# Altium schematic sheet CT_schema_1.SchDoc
size 405 x 258 mm
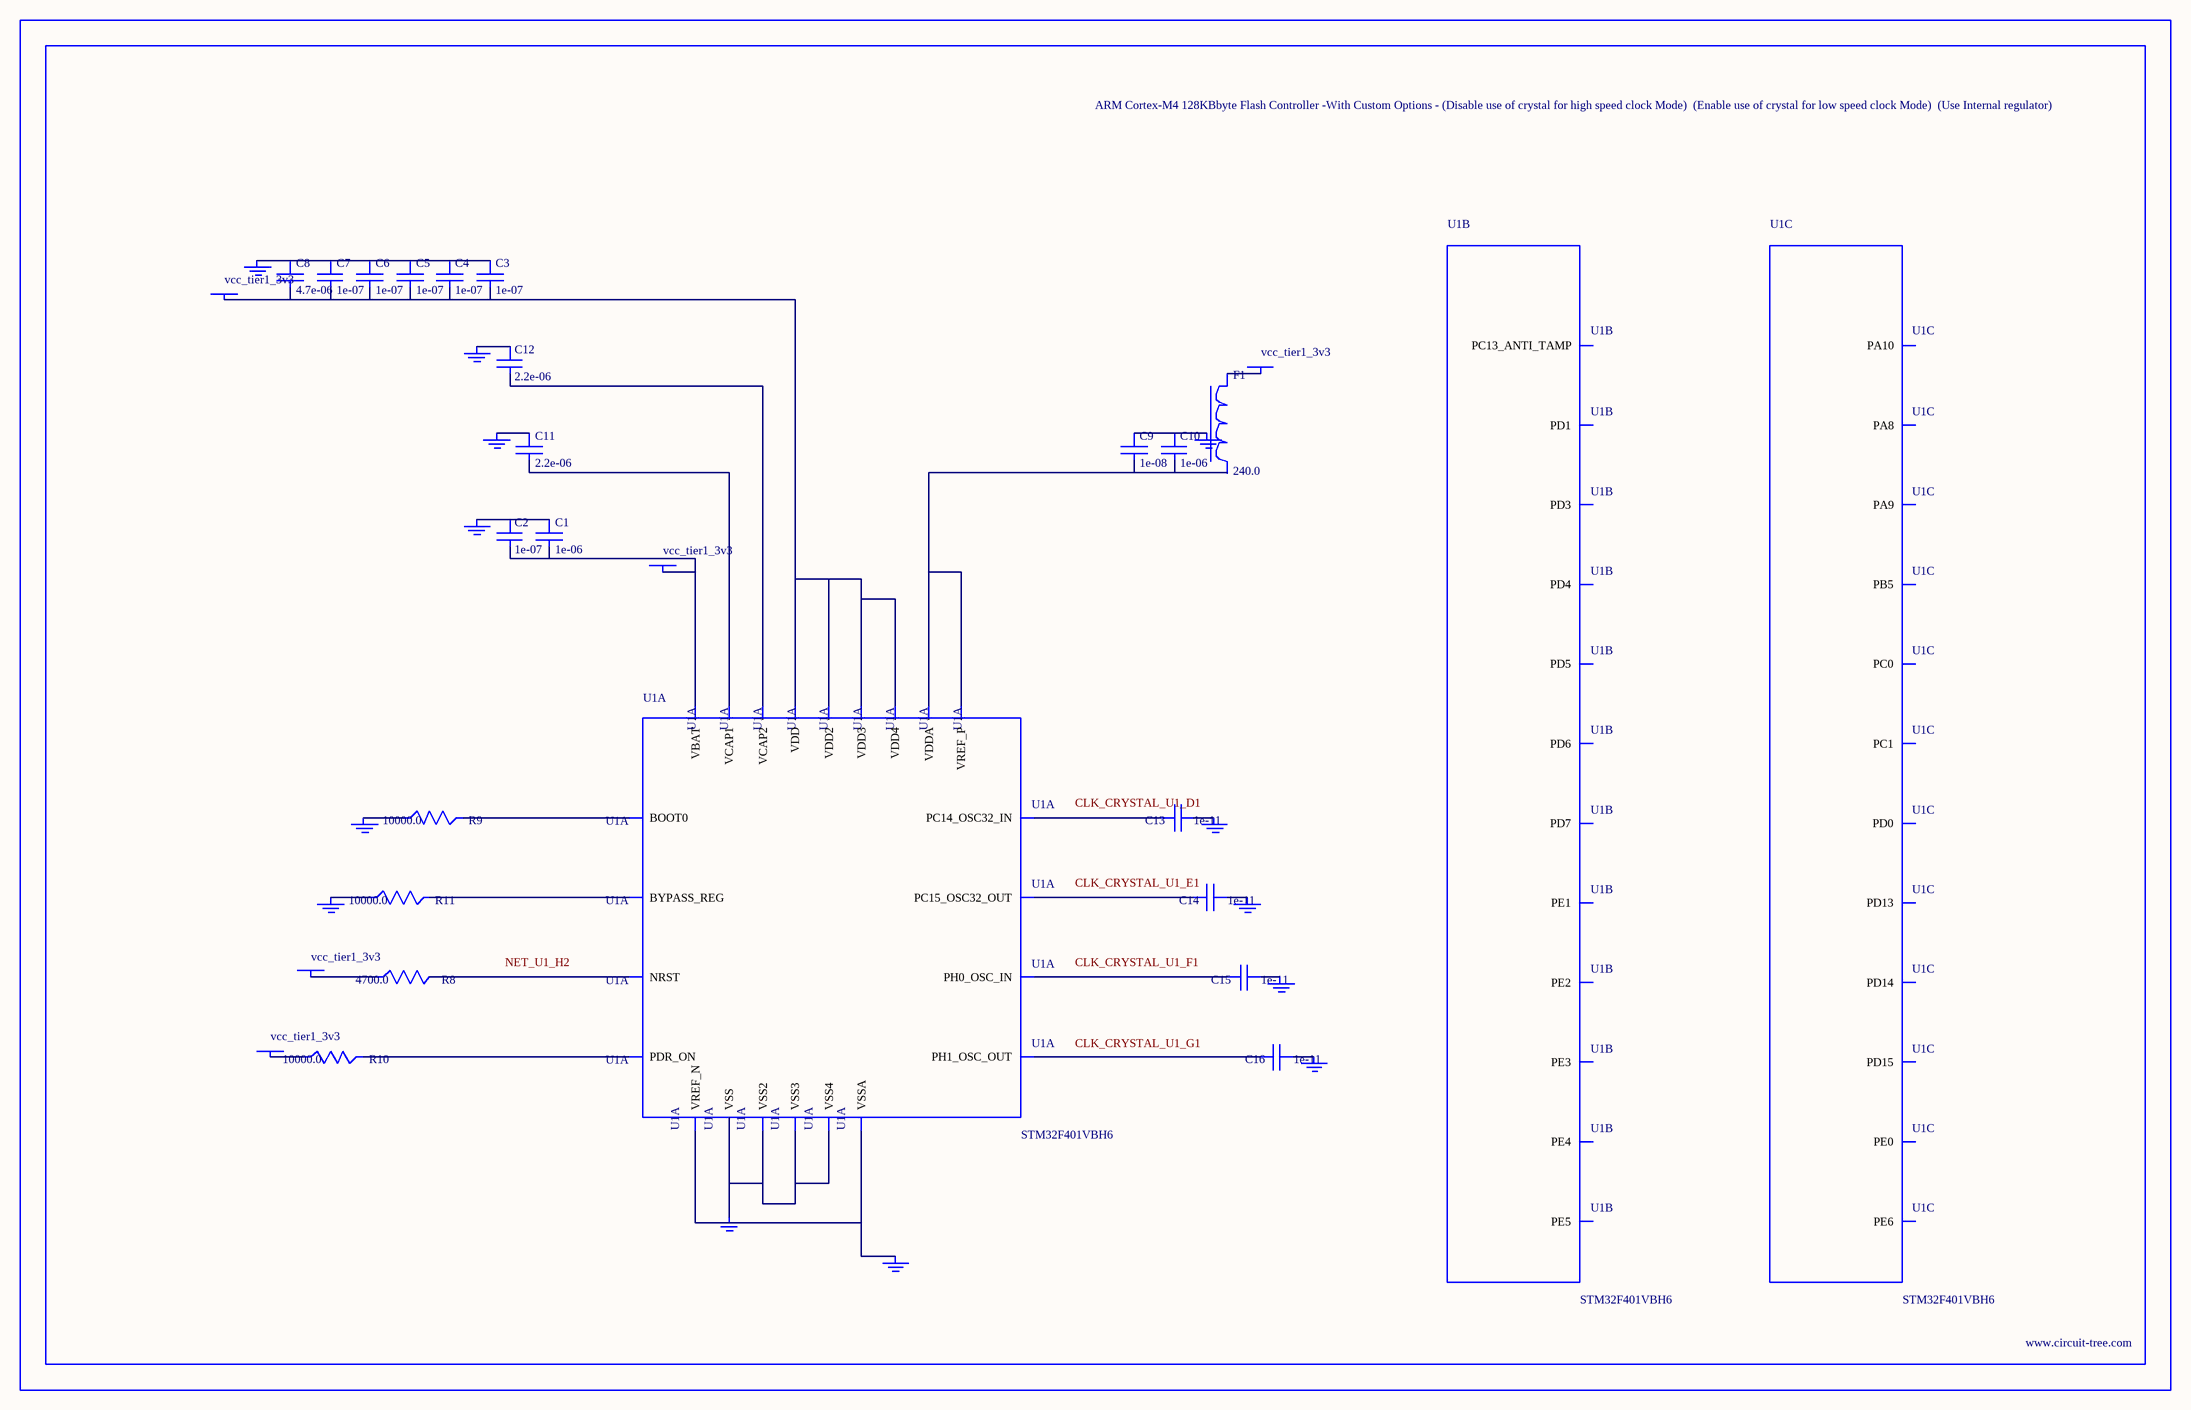
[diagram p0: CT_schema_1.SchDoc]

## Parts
BORDER0  (no value)
C1  1e-06  [C0603]
C2  1e-07  [C0603]
C3  1e-07  [C0603]
C4  1e-07  [C0603]
C5  1e-07  [C0603]
C6  1e-07  [C0603]
C7  1e-07  [C0603]
C8  4.7e-06  [C0603]
C9  1e-08  [C0603]
C10  1e-06  [C0603]
C11  2.2e-06  [C0603]
C12  2.2e-06  [C0603]
C13  1e-11  [C0402]
C14  1e-11  [C0402]
C15  1e-11  [C0402]
C16  1e-11  [C0402]
F1  240.0  [L0603]
GND_INSTANCE_0_0  (no value)
GND_INSTANCE_0_1  (no value)
GND_INSTANCE_0_2  (no value)
GND_INSTANCE_0_3  (no value)
GND_INSTANCE_0_4  (no value)
GND_INSTANCE_0_5  (no value)
GND_INSTANCE_0_6  (no value)
GND_INSTANCE_0_7  (no value)
GND_INSTANCE_0_8  (no value)
GND_INSTANCE_0_9  (no value)
GND_INSTANCE_0_10  (no value)
GND_INSTANCE_0_11  (no value)
GND_INSTANCE_0_12  (no value)
POWER_INSTANCE_0_0  vcc_tier1_3v3
POWER_INSTANCE_0_1  vcc_tier1_3v3
POWER_INSTANCE_0_2  vcc_tier1_3v3
POWER_INSTANCE_0_3  vcc_tier1_3v3
POWER_INSTANCE_0_4  vcc_tier1_3v3
R8  4700.0  [R0603]
R9  10000.0  [R0603]
R10  10000.0  [R0603]
R11  10000.0  [R0603]
U1  STM32F401VBH6  [UFBGA100]  (parts A,B,C of 8)

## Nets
NetC1_1: C1.1 C2.1 GND_INSTANCE_0_0.0(GND)
NetC1_2: C1.2 C2.2 POWER_INSTANCE_0_0.0(PWR) U1.E2(VBAT)
NetC3_1: C3.1 C4.1 C5.1 C6.1 C7.1 C8.1 GND_INSTANCE_0_2.0(GND)
NetC3_2: C3.2 C4.2 C5.2 C6.2 C7.2 C8.2 POWER_INSTANCE_0_2.0(PWR) U1.C4(VDD) U1.G2(VDD4) U1.G11(VDD2) U1.G12(VDD3)
NetC9_1: C9.1 C10.1 GND_INSTANCE_0_1.0(GND)
NetC9_2: C9.2 C10.2 U1.L1(VREF_P) U1.M1(VDDA)
NetC11_1: C11.1 GND_INSTANCE_0_5.0(GND)
NetC11_2: C11.2 U1.L11(VCAP1)
NetC12_1: C12.1 GND_INSTANCE_0_6.0(GND)
NetC12_2: C12.2 U1.C11(VCAP2)
NetC13_1: C13.1 GND_INSTANCE_0_7.0(GND)
NetC13_2: C13.2 U1.D1(PC14_OSC32_IN)
NetC14_1: C14.1 GND_INSTANCE_0_8.0(GND)
NetC14_2: C14.2 U1.E1(PC15_OSC32_OUT)
NetC15_1: C15.1 GND_INSTANCE_0_9.0(GND)
NetC15_2: C15.2 U1.F1(PH0_OSC_IN)
NetC16_1: C16.1 GND_INSTANCE_0_10.0(GND)
NetC16_2: C16.2 U1.G1(PH1_OSC_OUT)
NetF1_1: F1.1 POWER_INSTANCE_0_1.0(PWR)
NetGND_INSTANCE_0_3_0: GND_INSTANCE_0_3.0(GND) R9.1
NetGND_INSTANCE_0_4_0: GND_INSTANCE_0_4.0(GND) R11.1
NetGND_INSTANCE_0_11_0: GND_INSTANCE_0_11.0(GND) U1.J1(VSSA) U1.K1(VREF_N)
NetGND_INSTANCE_0_12_0: GND_INSTANCE_0_12.0(GND) U1.D3(VSS) U1.F2(VSS4) U1.F11(VSS2) U1.F12(VSS3)
NetPOWER_INSTANCE_0_3_0: POWER_INSTANCE_0_3.0(PWR) R10.1
NetPOWER_INSTANCE_0_4_0: POWER_INSTANCE_0_4.0(PWR) R8.1
NetR8_2: R8.2 U1.H2(NRST)
NetR9_2: R9.2 U1.A4(BOOT0)
NetR10_2: R10.2 U1.H3(PDR_ON)
NetR11_2: R11.2 U1.E3(BYPASS_REG)

Not connected (* = marked no-connect by the designer): F1 2; U1 A1(PE3) A2(PE1) A5(PD7) A6(PD5) B1(PE4) B2(PE2) B6(PD6) B7(PD4) B8(PD3) B9(PD1) C1(PC13_ANTI_TAMP) C2(PE5) C3(PE0) C5(PB5) C9(PD0) C12(PA10) D2(PE6) D10(PA9) D11(PA8) H1(PC0) H10(PD15) H11(PD14) H12(PD13) J2(PC1)

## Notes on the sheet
- Labels drawn without touching a wire or pin: CLK_CRYSTAL_U1_D1, CLK_CRYSTAL_U1_E1, CLK_CRYSTAL_U1_F1, CLK_CRYSTAL_U1_G1, NET_U1_H2

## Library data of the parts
BORDER0 = BORDER_PAGE0
C1 C10 = C0603C105K3RACTU
C2-C7 = 06035C104K4Z2A
C8 = GRM188R6YA475KE15D
C9 = 06035C103K4Z2A
C11 C12 = C0603C225K8RACTU
C13-C16 = C0402C100K3GACTU
F1 = Z0603C241ASMST
GND_INSTANCE_0_0-GND_INSTANCE_0_12 = GND
POWER_INSTANCE_0_0-POWER_INSTANCE_0_4 = PWR
R8 = RC0603JR-074K7L
R9-R11 = RC0603JR-0710KL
